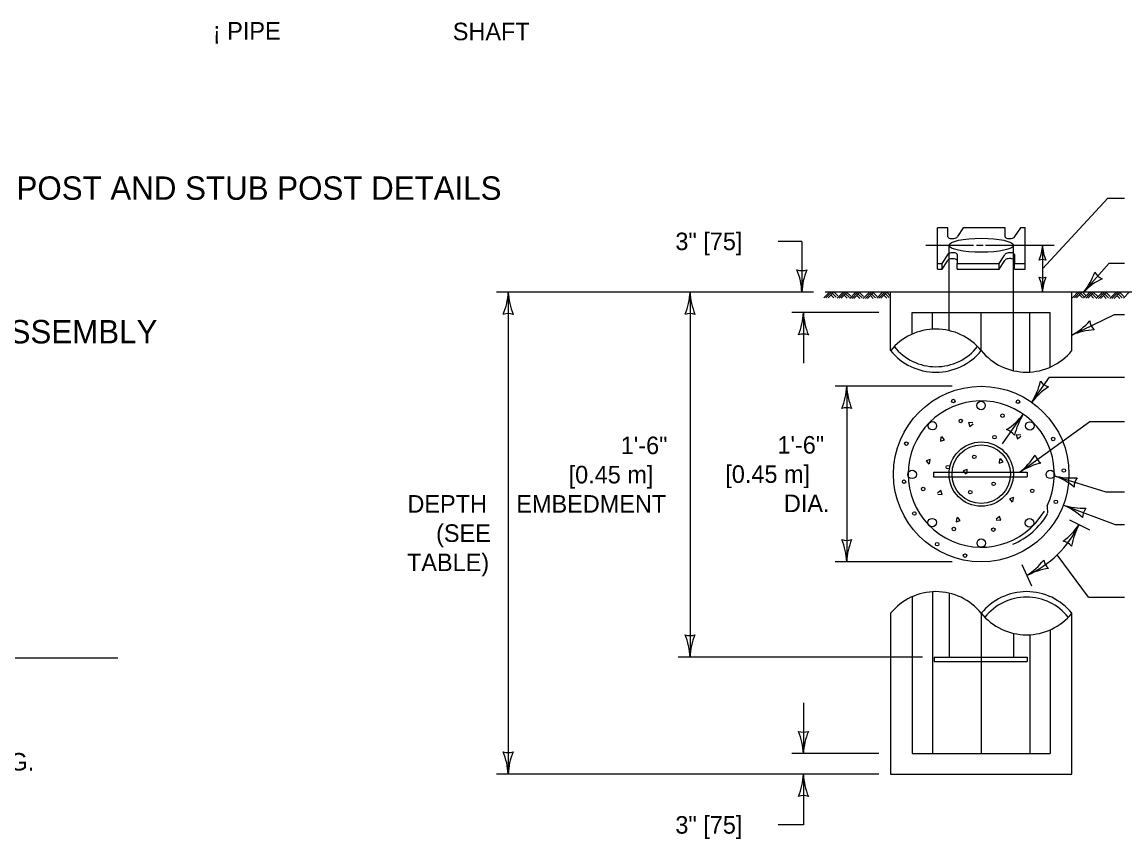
# Model space of a CAD drawing. Extents: x 49991 to 81321, y 49988 to 50028.
# Drawn here: x 50001.718 to 50005.489, y 49993.395 to 49996.187 of the extents above; entities that cross this region are included whole.
import ezdxf

# ---------------------------------------------------------------- set-up
doc = ezdxf.new("R2010")
doc.units = 0
for name, color, linetype in [('Level 1', 7, 'Continuous'), ('Level 2', 7, 'Continuous'), ('Level 3', 7, 'Continuous'), ('Level 4', 7, 'Continuous')]:
    doc.layers.add(name, color=color, linetype=linetype)

msp = doc.modelspace()

# ---------------------------------------------------------------- linework, layer by layer
at = {"layer": 'Level 1'}
for p, q in [((50004.8477, 49995.3416), (50004.8477, 49995.4829)), ((50004.8835, 49995.4829), (50004.8477, 49995.4829)), ((50004.8835, 49995.453), (50004.8835, 49995.4829)), ((50004.9357, 49995.4829), (50004.9161, 49995.4533)), ((50005.0792, 49995.4829), (50004.9357, 49995.4829)), ((50005.0792, 49995.453), (50005.0792, 49995.4829)), ((50005.1314, 49995.4829), (50005.1118, 49995.4534)), ((50005.1477, 49995.4829), (50005.1314, 49995.4829)), ((50005.1477, 49995.3416), (50005.1477, 49995.4829)), ((50004.8636, 49995.3616), (50004.8832, 49995.3911)), ((50004.8877, 49995.2637), (50004.8877, 49995.3758)), ((50004.9158, 49995.3917), (50004.9158, 49995.3616)), ((50005.0592, 49995.3616), (50005.0789, 49995.3912)), ((50005.1077, 49995.2637), (50005.1077, 49995.3758)), ((50005.1114, 49995.3917), (50005.1114, 49995.3616)), ((50004.8477, 49995.3616), (50004.8636, 49995.3616)), ((50004.8477, 49995.3416), (50004.8636, 49995.3416)), ((50004.8636, 49995.3416), (50004.8833, 49995.3712)), ((50004.8636, 49995.3416), (50004.8636, 49995.3616)), ((50004.9158, 49995.3616), (50005.0592, 49995.3616)), ((50004.9158, 49995.3416), (50004.9158, 49995.3616)), ((50004.9158, 49995.3416), (50005.0592, 49995.3416)), ((50005.0592, 49995.3416), (50005.0789, 49995.3712)), ((50005.0592, 49995.3416), (50005.0592, 49995.3616)), ((50005.1114, 49995.3616), (50005.1477, 49995.3616)), ((50005.1114, 49995.3416), (50005.1114, 49995.3616)), ((50005.1114, 49995.3416), (50005.1477, 49995.3416)), ((50004.4598, 49995.2441), (50004.4798, 49995.2641)), ((50005.531, 49995.2637), (50004.4643, 49995.2637)), ((50004.4668, 49995.2441), (50004.4868, 49995.2641)), ((50004.4738, 49995.2441), (50004.4938, 49995.2641)), ((50004.4889, 49995.2592), (50004.5019, 49995.2462)), ((50004.4938, 49995.2641), (50004.5068, 49995.2511)), ((50004.5046, 49995.2426), (50004.5246, 49995.2626)), ((50004.5116, 49995.2426), (50004.5316, 49995.2626)), ((50004.5186, 49995.2426), (50004.5386, 49995.2626)), ((50004.5386, 49995.2626), (50004.5516, 49995.2496)), ((50004.5479, 49995.2418), (50004.5679, 49995.2618)), ((50004.5549, 49995.2418), (50004.5749, 49995.2618)), ((50004.5619, 49995.2418), (50004.5819, 49995.2618)), ((50004.5819, 49995.2618), (50004.5949, 49995.2488)), ((50004.5944, 49995.242), (50004.6144, 49995.262)), ((50004.6014, 49995.242), (50004.6214, 49995.262)), ((50004.6084, 49995.242), (50004.6284, 49995.262)), ((50004.6284, 49995.262), (50004.6414, 49995.249)), ((50004.6405, 49995.2433), (50004.6605, 49995.2633)), ((50004.6475, 49995.2433), (50004.6675, 49995.2633)), ((50004.6545, 49995.2433), (50004.6745, 49995.2633)), ((50004.6745, 49995.2633), (50004.6875, 49995.2503)), ((50004.6877, 49995.0635), (50004.6877, 49995.2637)), ((50005.3076, 49995.0638), (50005.3076, 49995.2637)), ((50005.3092, 49995.2441), (50005.3292, 49995.2641)), ((50005.3162, 49995.2441), (50005.3362, 49995.2641)), ((50005.3232, 49995.2441), (50005.3432, 49995.2641)), ((50005.3383, 49995.2592), (50005.3513, 49995.2462)), ((50005.3432, 49995.2641), (50005.3562, 49995.2511)), ((50005.3479, 49995.2426), (50005.3679, 49995.2626)), ((50005.3549, 49995.2426), (50005.3749, 49995.2626)), ((50005.3619, 49995.2426), (50005.3819, 49995.2626)), ((50005.3819, 49995.2626), (50005.3949, 49995.2496)), ((50005.3912, 49995.2418), (50005.4112, 49995.2618)), ((50005.3982, 49995.2418), (50005.4182, 49995.2618)), ((50005.4052, 49995.2418), (50005.4252, 49995.2618)), ((50005.4252, 49995.2618), (50005.4382, 49995.2488)), ((50005.4377, 49995.242), (50005.4577, 49995.262)), ((50005.4447, 49995.242), (50005.4647, 49995.262)), ((50005.4517, 49995.242), (50005.4717, 49995.262)), ((50005.4717, 49995.262), (50005.4847, 49995.249)), ((50005.4838, 49995.2433), (50005.5038, 49995.2633)), ((50004.4839, 49995.2542), (50004.494, 49995.2441)), ((50004.5287, 49995.2527), (50004.5388, 49995.2426)), ((50004.5337, 49995.2577), (50004.5467, 49995.2447)), ((50004.572, 49995.2519), (50004.5821, 49995.2418)), ((50004.577, 49995.2569), (50004.59, 49995.2439)), ((50004.6185, 49995.2521), (50004.6286, 49995.242)), ((50004.6235, 49995.2571), (50004.6365, 49995.2441)), ((50004.6646, 49995.2534), (50004.6747, 49995.2433)), ((50004.6696, 49995.2584), (50004.6826, 49995.2454)), ((50005.3333, 49995.2542), (50005.3434, 49995.2441)), ((50005.372, 49995.2527), (50005.3821, 49995.2426)), ((50005.377, 49995.2577), (50005.39, 49995.2447)), ((50005.4153, 49995.2519), (50005.4254, 49995.2418)), ((50005.4203, 49995.2569), (50005.4333, 49995.2439)), ((50005.4618, 49995.2521), (50005.4719, 49995.242)), ((50005.4668, 49995.2571), (50005.4798, 49995.2441)), ((50004.7615, 49995.12), (50004.7615, 49995.1937)), ((50004.7615, 49995.1937), (50005.2339, 49995.1937)), ((50004.8306, 49995.1369), (50004.8306, 49995.1937)), ((50004.9977, 49995.0636), (50004.9977, 49995.1937)), ((50005.164, 49994.9904), (50005.164, 49995.1937)), ((50005.2339, 49995.0073), (50005.2339, 49995.1937)), ((50004.7615, 49994.2225), (50004.7615, 49993.686)), ((50004.8306, 49994.2394), (50004.8306, 49993.686)), ((50004.6877, 49994.1661), (50004.6877, 49993.616)), ((50004.9977, 49994.166), (50004.9977, 49993.686)), ((50005.3077, 49993.616), (50005.3077, 49994.166)), ((50005.164, 49994.0926), (50005.164, 49993.686)), ((50005.2339, 49994.1096), (50005.2339, 49993.686)), ((50004.7615, 49993.686), (50005.2339, 49993.686)), ((50004.6877, 49993.616), (50005.3077, 49993.616))]:
    msp.add_line(p, q, dxfattribs=at)
for points in [[(50004.9694, 49994.8169), (50004.9542, 49994.8184), (50004.9587, 49994.8048), (50004.9701, 49994.8139)], [(50004.86, 49994.7691), (50004.8585, 49994.7539), (50004.8721, 49994.7584), (50004.863, 49994.7698)], [(50005.1327, 49994.7744), (50005.1175, 49994.7759), (50005.122, 49994.7623), (50005.1334, 49994.7714)], [(50005.0605, 49994.694), (50005.059, 49994.6788), (50005.0726, 49994.6833), (50005.0635, 49994.6947)], [(50004.8212, 49994.6765), (50004.8227, 49994.6917), (50004.8091, 49994.6872), (50004.8182, 49994.6758)], [(50004.948, 49994.6423), (50004.9495, 49994.6575), (50004.9359, 49994.653), (50004.945, 49994.6416)], [(50004.8493, 49994.5732), (50004.8645, 49994.5717), (50004.86, 49994.5853), (50004.8486, 49994.5762)], [(50005.106, 49994.5466), (50005.1075, 49994.5618), (50005.0939, 49994.5573), (50005.103, 49994.5459)], [(50004.9139, 49994.4935), (50004.9124, 49994.4783), (50004.926, 49994.4828), (50004.9169, 49994.4942)], [(50005.0491, 49994.4851), (50005.0643, 49994.4836), (50005.0598, 49994.4972), (50005.0484, 49994.4881)]]:
    msp.add_lwpolyline(points, dxfattribs=at)
for centre, radius in [((50004.9977, 49994.6416), 0.3), ((50004.9025, 49994.8914), 0.00597), ((50004.997, 49994.8759), 0.0145), ((50005.1235, 49994.8891), 0.00597), ((50005.0704, 49994.8413), 0.00597), ((50004.8306, 49994.8069), 0.0145), ((50004.9276, 49994.8231), 0.00597), ((50005.164, 49994.8062), 0.0145), ((50005.043, 49994.7676), 0.00597), ((50004.7415, 49994.7456), 0.00597), ((50004.9977, 49994.6416), 0.11), ((50004.9977, 49994.6416), 0.1), ((50005.2435, 49994.7616), 0.00597), ((50004.974, 49994.7008), 0.00597), ((50004.8836, 49994.6651), 0.00597), ((50005.28, 49994.6537), 0.00597), ((50004.7339, 49994.6157), 0.00597), ((50004.7615, 49994.6406), 0.0145), ((50005.2339, 49994.6406), 0.0145), ((50004.7993, 49994.5907), 0.00597), ((50004.9603, 49994.58), 0.00597), ((50005.04, 49994.6081), 0.00597), ((50005.1721, 49994.5846), 0.00597), ((50005.2526, 49994.5466), 0.00597), ((50004.7689, 49994.5071), 0.00597), ((50004.8299, 49994.4758), 0.0145), ((50005.1625, 49994.475), 0.0145), ((50004.9041, 49994.454), 0.00597), ((50005.0392, 49994.4517), 0.00597), ((50004.8471, 49994.4023), 0.00597), ((50004.9977, 49994.4059), 0.0145), ((50004.942, 49994.3628), 0.00597)]:
    msp.add_circle(centre, radius, dxfattribs=at)
for centre, radius, start, end in [((50004.8427, 49994.9374), 0.1998, 39.1707, 140.8854), ((50004.8427, 49995.1899), 0.1814, 218.2801, 321.7479), ((50004.8426, 49995.1897), 0.1998, 219.1707, 320.8853), ((50005.1526, 49995.1899), 0.1998, 219.1707, 320.8792), ((50004.9977, 49994.6416), 0.25, 334.4169, 329.6548), ((50005.009, 49994.6325), 0.25, 292.7237, 329.6548), ((50004.8427, 49994.04), 0.1998, 39.116, 140.8635), ((50005.1527, 49994.04), 0.1998, 39.116, 140.884), ((50005.1527, 49994.04), 0.1813, 38.1825, 141.8162), ((50005.1527, 49994.2921), 0.1998, 219.116, 320.884)]:
    msp.add_arc(centre, radius, start, end, dxfattribs=at)
for centre, start_param, end_param in [((50004.8998, 49995.453), 0, 3.196704), ((50005.0955, 49995.453), 0, 3.215303), ((50004.8995, 49995.3917), 3.141593, 6.369528), ((50004.8996, 49995.3713), 3.252403, 6.298597), ((50005.0951, 49995.3917), 3.141593, 6.3597), ((50005.0951, 49995.3717), 3.146139, 6.3597)]:
    msp.add_ellipse(centre, major_axis=(-0.0163, 0), ratio=0.4, start_param=start_param, end_param=end_param, dxfattribs=at)
msp.add_spline([(50005.2247, 49994.5066), (50005.225, 49994.517), (50005.2232, 49994.5336)], degree=3, dxfattribs=at)
at = {"layer": 'Level 2'}
msp.add_line((50000.9845, 49994.0131), (50002.0451, 49994.0131), dxfattribs=at)
at = {"layer": 'Level 3'}
for p, q in [((50005.2072, 49995.3437), (50005.4302, 49995.5847)), ((50005.4302, 49995.5847), (50005.4873, 49995.5847)), ((50004.3843, 49995.4371), (50004.3029, 49995.4371)), ((50004.3843, 49995.4371), (50004.3843, 49995.2637)), ((50004.8077, 49995.4237), (50004.9716, 49995.4237)), ((50004.9815, 49995.4237), (50005.0043, 49995.4237)), ((50005.0119, 49995.4237), (50005.2472, 49995.4237)), ((50005.2072, 49995.4237), (50005.2072, 49995.2637)), ((50005.3478, 49995.2637), (50005.4356, 49995.3621)), ((50005.4356, 49995.3621), (50005.4873, 49995.3621)), ((50004.4243, 49995.2637), (50003.3401, 49995.2637)), ((50003.3801, 49995.2637), (50003.3801, 49993.616)), ((50004.0019, 49995.2637), (50004.0019, 49994.016)), ((50004.6477, 49995.1937), (50004.3497, 49995.1937)), ((50004.3897, 49995.1937), (50004.3897, 49995.0203)), ((50005.3076, 49995.1169), (50005.4537, 49995.1873)), ((50005.4537, 49995.1873), (50005.4873, 49995.1873)), ((50005.1703, 49994.8871), (50005.2308, 49994.9731)), ((50005.2308, 49994.9731), (50005.4873, 49994.9731)), ((50004.8977, 49994.9416), (50004.4977, 49994.9416)), ((50004.5377, 49994.9416), (50004.5377, 49994.3416)), ((50005.0705, 49994.7452), (50005.1415, 49994.8461)), ((50005.1301, 49994.6483), (50005.3693, 49994.8214)), ((50005.3693, 49994.8214), (50005.4873, 49994.8214)), ((50005.2476, 49994.6359), (50005.4234, 49994.5804)), ((50005.4234, 49994.5804), (50005.4873, 49994.5804)), ((50005.2784, 49994.5358), (50005.4554, 49994.469)), ((50005.2997, 49994.4855), (50005.3676, 49994.4506)), ((50005.4554, 49994.469), (50005.4873, 49994.469)), ((50005.364, 49994.2208), (50005.2574, 49994.3655)), ((50004.8977, 49994.3416), (50004.4977, 49994.3416)), ((50005.1703, 49994.2588), (50005.1373, 49994.3316)), ((50005.364, 49994.2208), (50005.4873, 49994.2208)), ((50004.7968, 49994.016), (50003.9619, 49994.016)), ((50004.3897, 49993.8594), (50004.3897, 49993.686)), ((50004.6477, 49993.686), (50004.3497, 49993.686)), ((50004.6477, 49993.616), (50003.3401, 49993.616)), ((50004.3897, 49993.616), (50004.3897, 49993.4426)), ((50004.3897, 49993.4426), (50004.3029, 49993.4426))]:
    msp.add_line(p, q, dxfattribs=at)
for centre, radius, start, end in [((50005.0591, 49995.4299), 0.1482, 337.456, 357.6395), ((50005.3623, 49995.4314), 0.1553, 182.8273, 202.0772), ((50005.2072, 49995.3383), 0.0365, 72.1388, 107.8612), ((50004.3843, 49995.392), 0.0548, 252.1388, 287.8612), ((50004.1516, 49995.2523), 0.233, 2.8273, 22.0772), ((50004.6064, 49995.2546), 0.2223, 157.456, 177.6395), ((50005.2072, 49995.3492), 0.0365, 252.1388, 287.8612), ((50005.0521, 49995.2561), 0.1553, 2.8273, 22.0772), ((50005.3553, 49995.2576), 0.1482, 157.456, 177.6395), ((50005.1665, 49995.4101), 0.233, 321.0855, 340.3354), ((50005.5075, 49995.109), 0.2223, 115.7142, 135.8977), ((50005.4332, 49995.3594), 0.0548, 210.397, 246.1194), ((50003.158, 49995.2729), 0.2223, 337.456, 357.6395), ((50003.6128, 49995.2752), 0.233, 182.8273, 202.0772), ((50003.7798, 49995.2729), 0.2223, 337.456, 357.6395), ((50004.2346, 49995.2752), 0.233, 182.8273, 202.0772), ((50003.3801, 49995.1355), 0.0548, 72.1388, 107.8612), ((50004.0019, 49995.1355), 0.0548, 72.1388, 107.8612), ((50004.1676, 49995.2029), 0.2223, 337.456, 357.6395), ((50004.6224, 49995.2052), 0.233, 182.8273, 202.0772), ((50005.1961, 49995.3215), 0.233, 298.5829, 317.8328), ((50005.4231, 49995.1726), 0.0548, 187.8944, 223.6168), ((50004.3897, 49995.0655), 0.0548, 72.1388, 107.8612), ((50005.3959, 49994.9128), 0.2223, 93.2116, 113.3951), ((50004.9733, 49995.0115), 0.233, 327.7137, 346.9635), ((50005.244, 49994.9919), 0.0548, 217.0252, 252.7475), ((50004.3156, 49994.9508), 0.2223, 337.456, 357.6395), ((50004.7704, 49994.9531), 0.233, 182.8273, 202.0772), ((50005.3467, 49994.7518), 0.2223, 122.3424, 142.5259), ((50004.5377, 49994.8134), 0.0548, 72.1388, 107.8612), ((50004.9651, 49994.9814), 0.2223, 302.3424, 322.5259), ((50005.3385, 49994.7217), 0.233, 147.7137, 166.9635), ((50005.0678, 49994.7413), 0.0548, 37.0252, 72.7475), ((50004.9843, 49994.83), 0.233, 308.7282, 327.978), ((50005.234, 49994.7234), 0.0548, 198.0397, 233.7621), ((50005.2529, 49994.4629), 0.2223, 103.3569, 123.5404), ((50005.172, 49994.4269), 0.2223, 49.9369, 70.1204), ((50005.3067, 49994.8613), 0.233, 255.3082, 274.5581), ((50005.3699, 49994.5973), 0.0548, 144.6197, 180.3421), ((50005.1914, 49994.3312), 0.2223, 46.7913, 66.9748), ((50005.3498, 49994.7576), 0.233, 252.1626, 271.4125), ((50005.3984, 49994.4905), 0.0548, 141.4741, 177.1965), ((50005.0045, 49994.6266), 0.3635, 294.2563, 334.2874), ((50005.1474, 49994.5928), 0.2223, 305.9375, 326.121), ((50005.5364, 49994.357), 0.233, 151.3088, 170.5586), ((50004.5377, 49994.4699), 0.0548, 252.1388, 287.8612), ((50004.305, 49994.3302), 0.233, 2.8273, 22.0772), ((50004.7598, 49994.3325), 0.2223, 157.456, 177.6395), ((50005.265, 49994.3596), 0.0548, 40.6203, 76.3426), ((50005.0273, 49994.4909), 0.233, 302.8816, 322.1315), ((50005.2572, 49994.0984), 0.2223, 97.5103, 117.6938), ((50005.2648, 49994.3594), 0.0548, 192.1931, 227.9155), ((50004.0019, 49994.1443), 0.0548, 252.1388, 287.8612), ((50003.7692, 49994.0046), 0.233, 2.8273, 22.0772), ((50004.224, 49994.0069), 0.2223, 157.456, 177.6395), ((50004.3897, 49993.8143), 0.0548, 252.1388, 287.8612), ((50004.157, 49993.6746), 0.233, 2.8273, 22.0772), ((50004.6118, 49993.6769), 0.2223, 157.456, 177.6395), ((50003.3801, 49993.7443), 0.0548, 252.1388, 287.8612), ((50003.1474, 49993.6046), 0.233, 2.8273, 22.0772), ((50003.6022, 49993.6069), 0.2223, 157.456, 177.6395), ((50004.1676, 49993.6252), 0.2223, 337.456, 357.6395), ((50004.6224, 49993.6275), 0.233, 182.8273, 202.0772), ((50004.3897, 49993.4878), 0.0548, 72.1388, 107.8612)]:
    msp.add_arc(centre, radius, start, end, dxfattribs=at)
at = {"layer": 'Level 4'}
for p, q in [((50004.8877, 49995.3758), (50004.8877, 49995.4237)), ((50005.1077, 49995.3758), (50005.1077, 49995.4237)), ((50004.8877, 49995.1321), (50004.8877, 49995.2637)), ((50005.1077, 49994.9951), (50005.1077, 49995.2637)), ((50004.8344, 49994.6482), (50005.1543, 49994.6482)), ((50004.8344, 49994.6482), (50004.8344, 49994.6327)), ((50004.8344, 49994.6327), (50005.1543, 49994.6327)), ((50005.1543, 49994.6482), (50005.1543, 49994.6327)), ((50004.8877, 49994.2346), (50004.8877, 49994.016)), ((50005.1077, 49994.0974), (50005.1077, 49994.016)), ((50004.8368, 49994.016), (50005.1543, 49994.016)), ((50004.8368, 49994.016), (50004.8368, 49994.0005)), ((50005.1543, 49994.016), (50005.1543, 49994.0005)), ((50004.8368, 49994.0005), (50005.1543, 49994.0005))]:
    msp.add_line(p, q, dxfattribs=at)
msp.add_ellipse((50004.9977, 49995.4237), major_axis=(0.11, 0), ratio=0.218186, dxfattribs=at)

# ---------------------------------------------------------------- texts
at = {"layer": 'Level 2'}
for s, height, p in [('¡ PIPE', 0.06, (50002.3703, 49996.1267)), ('SHAFT', 0.06, (50003.1907, 49996.1245)), ('SIGN POST AND STUB POST DETAILS', 0.08, (50001.4076, 49995.5791)), ('3" [75]', 0.06, (50003.9518, 49995.4071)), ('PROCEDURE FOR BASE CONNECTION ASSEMBLY', 0.08, (49999.5711, 49995.0883)), ('1\'-6"', 0.06, (50003.765, 49994.7098)), ('1\'-6"', 0.06, (50004.3008, 49994.7116)), ('[0.45 m]', 0.06, (50003.5867, 49994.6098)), ('[0.45 m]', 0.06, (50004.1225, 49994.6116)), ('DEPTH', 0.06, (50003.0356, 49994.5098)), ('EMBEDMENT', 0.06, (50003.4079, 49994.5098)), ('DIA.', 0.06, (50004.3229, 49994.5116)), ('(SEE', 0.06, (50003.1336, 49994.4098)), ('TABLE)', 0.06, (50003.0341, 49994.3098)), ('   A CENTER PUNCH TO PREVENT NUT LOOSENING.   ', 0.06, (49999.7355, 49993.6283)), ('3" [75]', 0.06, (50003.9518, 49993.4126))]:
    msp.add_text(s, height=height, dxfattribs=at).set_placement(p)

doc.saveas('drawing.dxf')
